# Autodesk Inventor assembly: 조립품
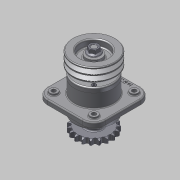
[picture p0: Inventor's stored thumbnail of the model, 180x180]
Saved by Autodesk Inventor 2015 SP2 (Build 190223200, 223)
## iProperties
Created: 2015-07
Part Number: 조립품
Document SubType Name: Assembly
Designer: AMC
Author: AMC
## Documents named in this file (12)
- C:\Users\AMC\Desktop\450735V1005\조립품.iam
- C:\Users\AMC\Desktop\450735V1005\본체2.ipt
- C:\Users\AMC\Desktop\450735V1005\2-커버.ipt
- C:\Users\AMC\Desktop\450735V1005\3-축.ipt
- C:\Users\AMC\Desktop\450735V1005\4-V벨트풀리.ipt
- C:\Users\AMC\Desktop\450735V1005\5-체인 스프로킷.ipt
- C:\Users\AMC\Desktop\450735V1005\6-베어링 6206.ipt
- C:\Users\AMC\Desktop\450735V1005\7-부시.ipt
- C:\Users\AMC\Desktop\450735V1005\8-오일실 30x42.ipt
- C:\Users\AMC\Desktop\450735V1005\9-M16-너트.ipt
- C:\Users\AMC\Desktop\450735V1005\10-M6.ipt
- C:\Users\AMC\Desktop\450735V1005\11-키 6x6.ipt
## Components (22 placed, 10 different names)
1. 2-커버:1
2. 3-축:1
3. 4-V벨트풀리:1
4. 5-체인 스프로킷:1
5. 6-베어링 6206:1
6. 7-부시:1
7. 8-8-오일실 30x42:1
8. 9-M16 너트:1
9. 10-M6:1
10. 11-키 6x6:1
11. 2-커버:2
12. 6-베어링 6206:2
13. 10-M6:2
14. 10-M6:3
15. 10-M6:4
16. 10-M6:5
17. 10-M6:6
18. 10-M6:7
19. 10-M6:8
20. 8-8-오일실 30x42:2
21. 11-키 6x6:2
22. 9-M16 너트:2
